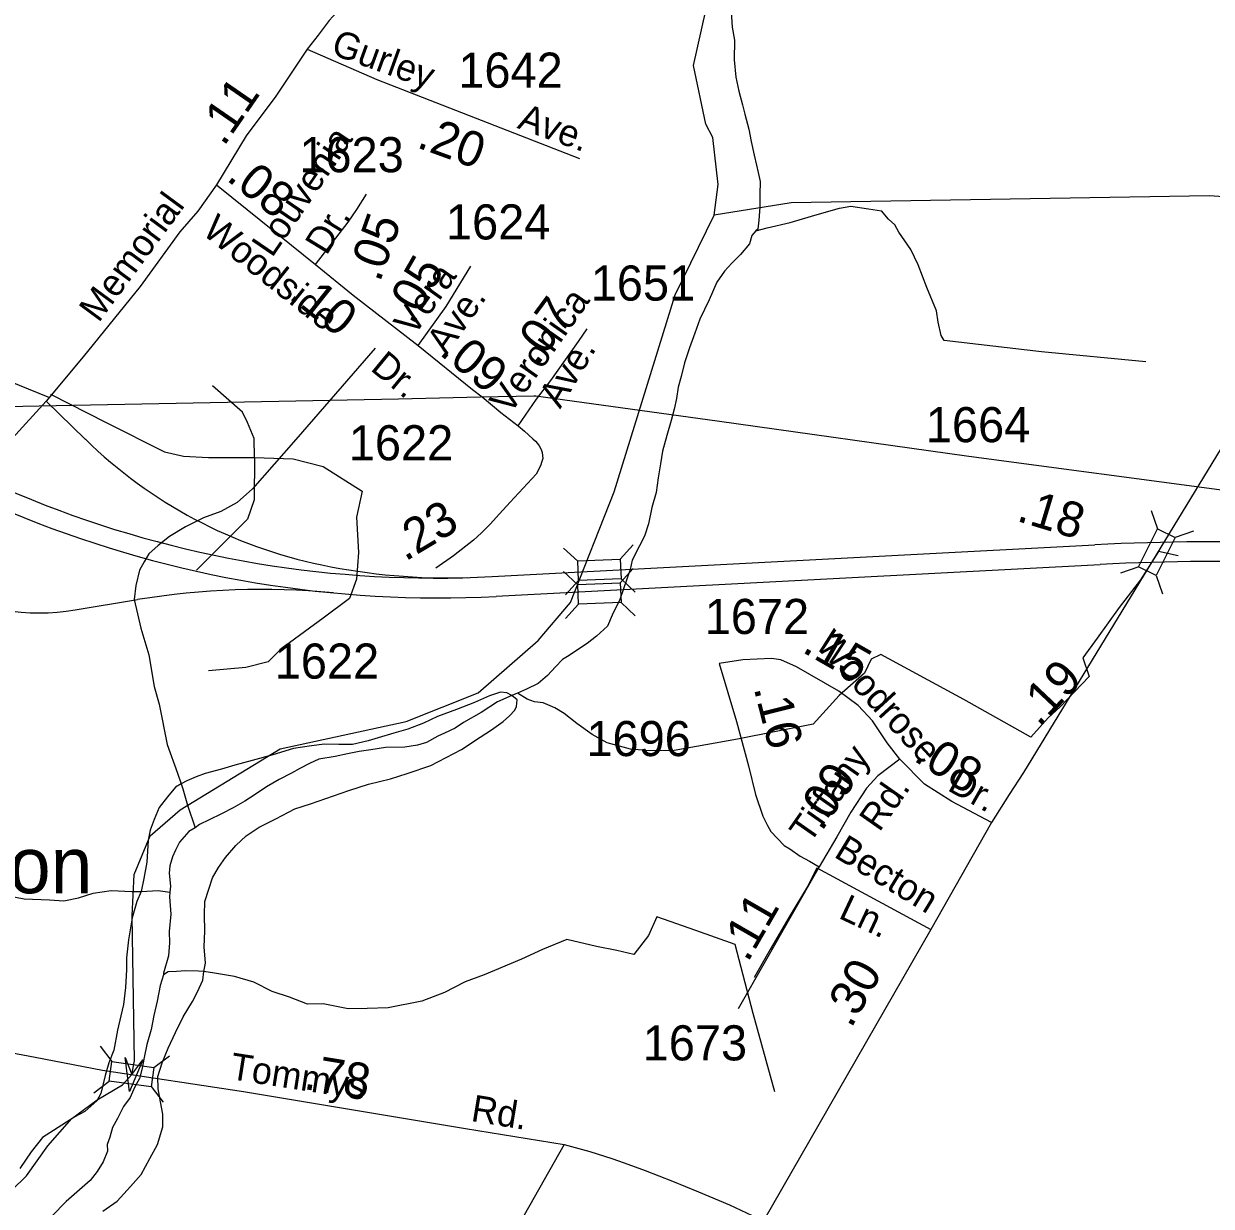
# Model space of a CAD drawing. Extents: x 2315291 to 2336543, y 597177 to 615230.
# Drawn here: x 2317521 to 2321750, y 606517 to 610727 of the extents above; entities that cross this region are included whole.
import ezdxf

# ---------------------------------------------------------------- set-up
doc = ezdxf.new("R2010")
doc.units = 0
for name, color, linetype in [('Exist Civil Demographics Community Label', 7, 'Continuous'), ('Exist Hydrographic Creek Single Shore', 7, 'Continuous'), ('Exist Hydrographic Misc Water Feature', 7, 'Continuous'), ('Exist Road Non-System Type 51', 7, 'Continuous'), ('Exist Road Non-System Type 51 Label', 7, 'Continuous'), ('Exist Road Primary US Attributed', 7, 'Continuous'), ('Exist Road Secondary Mileage Hundredths English Label', 7, 'Continuous'), ('Exist Road Secondary Structure Standard Bridge Attributed CELL', 7, 'Continuous'), ('Exist Road Secondary Structure Standard Bridge CELL', 7, 'Continuous'), ('Exist Road Secondary Type 51 Attributed', 7, 'Continuous'), ('Exist Road Secondary Type 51 Label', 7, 'Continuous'), ('Exist Road Secondary Type 51 Number Label', 7, 'Continuous'), ('Exist Utilities Electrical Transmission Line', 7, 'Continuous')]:
    doc.layers.add(name, color=color, linetype=linetype)

msp = doc.modelspace()

# ---------------------------------------------------------------- linework, layer by layer
at = {"layer": 'Exist Hydrographic Creek Single Shore'}
for points in [[(2319979.2, 610046.1), (2319994.3, 610155), (2319975.3, 610321.6), (2319950.2, 610369.8), (2319906.2, 610578.1), (2319995.9, 610982.4), (2320039.3, 611136.1), (2319944.8, 611360.6), (2319982.2, 611602.9), (2319883.7, 611839.2)], [(2317204.2, 606258.5), (2317425.2, 606522.7), (2317529.8, 606625.3), (2317606.2, 606732), (2317692.2, 606828.6), (2317781.7, 606896), (2317872.2, 606949.3), (2317905.4, 606985.5), (2317914.4, 607034.8), (2317906.3, 607550.3), (2317913.3, 607698.2), (2317970.3, 607835.1), (2318077.3, 607928.1), (2318433.3, 608145.9), (2318882.1, 608242.8), (2319139.3, 608345), (2319353.1, 608531), (2319468.2, 608666.9), (2319623.2, 609060.4), (2319840.3, 609761.6), (2319979.2, 610046.1)]]:
    msp.add_lwpolyline(points, dxfattribs=at)
at = {"layer": 'Exist Hydrographic Misc Water Feature'}
for points in [[(2320031.5, 610941.8), (2320034.7, 610910.4), (2320033.7, 610840.4), (2320040.5, 610770.5), (2320043.3, 610714.5), (2320051.5, 610668.6), (2320050.5, 610598.7), (2320057.1, 610536.8), (2320067.5, 610487), (2320080, 610438.9), (2320088.5, 610405.1), (2320102.8, 610351.5), (2320111.2, 610307.6), (2320121.9, 610259.4), (2320130.5, 610223.7), (2320136.8, 610197.9), (2320143, 610165.8), (2320141.6, 610119.8), (2320142, 610073.9), (2320138.7, 610027.7), (2320134.6, 609995.9), (2320128.4, 609990)], [(2322074.8, 610085.2), (2322043.2, 610093.6), (2321744.2, 610114.3), (2320253.3, 610090), (2319979.2, 610046.1)], [(2320128.4, 609990), (2320168.8, 610000.1), (2320250.2, 610019.1), (2320326.3, 610042.1), (2320388, 610060.4), (2320426, 610070.9), (2320465.7, 610077.5), (2320529.5, 610068.3), (2320575.5, 610060.6)], [(2321517.1, 609523), (2321145.3, 609559.1), (2320798.8, 609599.1), (2320788.5, 609617.3), (2320777.8, 609665.1), (2320771.3, 609705), (2320736.8, 609788.5), (2320705.9, 609868.2), (2320679.4, 609923.7), (2320637, 609985.2), (2320622.4, 610010.9), (2320600.3, 610030.9), (2320575.5, 610060.6)], [(2320128.4, 609990), (2320113.1, 609973.6), (2320105.5, 609943.5), (2320073.7, 609905.3), (2320042.3, 609874.8), (2320016.3, 609846.6), (2319989.2, 609806.5), (2319961.3, 609744.2), (2319928.3, 609675.8), (2319911.1, 609625.6), (2319891.4, 609573.5), (2319873.8, 609519.3), (2319862.5, 609471.2), (2319851, 609433.1), (2319845.7, 609393), (2319837.5, 609354.9), (2319826.2, 609314.8), (2319810.8, 609260.7), (2319795.6, 609204.7), (2319788.3, 609160.7), (2319780.3, 609110.4), (2319772.9, 609058.4), (2319757.5, 609004.3), (2319746.2, 608946.5), (2319730.8, 608902.1), (2319713.2, 608867.9), (2319687.8, 608817.7), (2319680, 608783.6), (2319668.5, 608749.7), (2319656.8, 608715.4), (2319643.3, 608677.3), (2319616, 608620.9), (2319600.2, 608582.7), (2319560.6, 608546.6), (2319527, 608520), (2319489.3, 608495.6), (2319463.5, 608477.7), (2319439.7, 608463.3), (2319414, 608436.8), (2319386.2, 608406.6), (2319352.5, 608378.4), (2319310.9, 608357.9), (2319279.1, 608343.5)], [(2318772, 609571.6), (2318489.7, 609246.7), (2318335.5, 609071.2), (2318280.3, 609022.3), (2318222.7, 608990), (2318161, 608967.3), (2318097.2, 608936.3), (2318039.6, 608902), (2317999.8, 608869.5), (2317966.4, 608839.2), (2317948.9, 608811), (2317932.7, 608781), (2317919.6, 608726.6), (2317914.3, 608676.8), (2317937.3, 608575.1), (2317966.4, 608479.5), (2317985.6, 608367.5), (2318002.3, 608303.8), (2318031.8, 608160.2), (2318068.5, 608058.6), (2318080.8, 608020.6)], [(2321632.5, 608832.4), (2321562.4, 608847.9), (2321497.6, 608747.3), (2321422.5, 608648.3), (2321343.8, 608539.7), (2321292.5, 608469.2), (2321315.5, 608403.3), (2321212.3, 608294.3), (2321168.9, 608255.8), (2321107.8, 608187.1), (2320868.7, 608320.5), (2320572.8, 608481.4)], [(2320572.8, 608481.4), (2320539.2, 608465), (2320515.4, 608414.6), (2320424.5, 608335.8), (2320331.6, 608233), (2320062.4, 608180.2), (2319837.3, 608139.5), (2319750.7, 608138.8), (2319681, 608143.9), (2319598.6, 608166.9), (2319544.5, 608196.5), (2319489.9, 608236), (2319445.6, 608271.5), (2319411.6, 608291.2), (2319371, 608308.6), (2319339.4, 608312.2), (2319313.4, 608321.8), (2319279.1, 608343.5)], [(2319259, 608335.2), (2319241.2, 608345.2), (2319218.8, 608346.9), (2319179.5, 608334.2), (2319125.5, 608309.9), (2319061.6, 608285.1), (2318993.7, 608260.4), (2318944.3, 608236.2), (2318888.5, 608215.4), (2318838.5, 608201), (2318782.9, 608184.2), (2318746.8, 608173.9), (2318691.2, 608161.2), (2318643, 608160.7), (2318591.2, 608162.4), (2318545.4, 608155.9), (2318481.5, 608146.9), (2318407.4, 608124.3), (2318333.8, 608103.4), (2318272.5, 608086.7), (2318224.5, 608072.4), (2318166.5, 608057.6), (2318134.7, 608045.4), (2318100.9, 608031), (2318080.8, 608020.6)], [(2319259, 608335.2), (2319207.8, 608312.5), (2319149.9, 608274.2), (2319086.4, 608239.5), (2319056.6, 608219.3), (2319018.7, 608200.7), (2318994.9, 608190.5), (2318954.9, 608168.1), (2318923.1, 608157.9), (2318877.4, 608151.4), (2318809.3, 608150.6), (2318757.3, 608141.9), (2318715.4, 608135.6), (2318673.6, 608127.3), (2318629.7, 608118.5), (2318571.9, 608108.1), (2318538.1, 608093.7), (2318504.4, 608075.3), (2318474.5, 608059.1), (2318430.8, 608036.5), (2318384.7, 608010.2), (2318341.4, 607979.8), (2318307.8, 607959.3), (2318266, 607934.8), (2318224.3, 607914.3), (2318180.6, 607892.1), (2318146.8, 607875.7), (2318130.8, 607863.5)], [(2318162, 607351.9), (2318167.9, 607382.2), (2318163.2, 607440.1), (2318164.9, 607495.8), (2318163.8, 607553.9), (2318165.5, 607602), (2318179.2, 607646.1), (2318192.7, 607686.3), (2318214.5, 607722.3), (2318239.5, 607758.7), (2318275.6, 607801.1), (2318313.1, 607835.2), (2318358.6, 607866.1), (2318418.5, 607896.4), (2318486, 607931.3), (2318541.7, 607949.6), (2318678.7, 607997.2), (2318748.8, 608019.9), (2318826.4, 608039), (2318886.4, 608057.6), (2318969.9, 608086.4), (2319079.2, 608143.3), (2319146.6, 608186.3), (2319186.4, 608212.7), (2319228.1, 608243), (2319250, 608263.2), (2319269.5, 608283.4), (2319275.4, 608295.5), (2319277.3, 608319.5), (2319259, 608335.2)], [(2319279.1, 608343.5), (2319272.8, 608341.7), (2319259, 608335.2)], [(2318080.8, 608020.6), (2318061.5, 608008.5), (2318032, 607974.5), (2318002.3, 607936), (2317984.6, 607894), (2317971.1, 607855.9), (2317963.3, 607819.7), (2317958.4, 607741.8), (2317948.7, 607683.6), (2317939.3, 607637.6)], [(2318080.8, 608020.6), (2318087.4, 608003.1), (2318104, 607945), (2318130.8, 607863.5)], [(2318130.8, 607863.5), (2318108.9, 607851.4), (2318075.3, 607813), (2318061.5, 607784.7), (2318049.8, 607760.5), (2318040.4, 607728.6), (2318038.5, 607702.6), (2318043.3, 607656.5), (2318041.2, 607634.4)], [(2316547.6, 607694.6), (2316633.1, 607733.3), (2316704.3, 607768.3), (2316748.6, 607780.8), (2316782.2, 607789.1), (2316788.1, 607786.9), (2316880.2, 607778), (2316966.5, 607760.9), (2317040.4, 607749.8), (2317080.7, 607724.2), (2317145.3, 607693.1), (2317195.2, 607675.4), (2317241.5, 607657.9), (2317305.7, 607632.8), (2317381.6, 607631.6), (2317441.4, 607626.2), (2317521.8, 607611.3), (2317611.8, 607607.8), (2317663.5, 607604.5), (2317715.8, 607615.3), (2317767.5, 607631.9), (2317831.4, 607640.5), (2317905.3, 607637.1), (2317939.3, 607637.6)], [(2317939.3, 607637.6), (2317923.5, 607601.5), (2317906.3, 607543.2), (2317893.2, 607464.9), (2317886, 607401.1), (2317886.2, 607358.9), (2317882.7, 607295.3), (2317875.7, 607235.1), (2317866.1, 607194.8), (2317854.8, 607143), (2317841.5, 607072.8), (2317824.1, 607026.8), (2317810.3, 606982.6), (2317794.9, 606918.4), (2317781.2, 606892.1), (2317737.9, 606853.6), (2317702.3, 606835.5), (2317626.4, 606786.4), (2317587, 606761.9), (2317547.4, 606709.9), (2317506.2, 606651.3)], [(2317939.3, 607637.6), (2317999.4, 607640.4), (2318041.2, 607634.4)], [(2318041.2, 607634.4), (2318039.4, 607618.5), (2318044.5, 607556.5), (2318038.8, 607494.5), (2318039.4, 607454.6), (2318035.5, 607408.6), (2318018.5, 607346.7), (2318018.2, 607340.6)], [(2320195.5, 606924.1), (2320118.8, 607203.4), (2320054, 607448.3), (2319913.7, 607498.6), (2319775.1, 607547.4), (2319745.8, 607480.9), (2319692.9, 607412.6), (2319632.8, 607427.7), (2319560.2, 607441.1), (2319454.4, 607465.9), (2319368.7, 607431), (2319293.3, 607396.1), (2319159.8, 607340.7), (2319092.5, 607316), (2319088.2, 607313.8), (2319018.5, 607277.3), (2318938.9, 607246.3), (2318819, 607223.3), (2318743.3, 607220.2), (2318675.6, 607219.8), (2318587.1, 607236.8), (2318531.3, 607236.3), (2318467.1, 607261.3), (2318404.8, 607280.8), (2318340.2, 607314.1), (2318270.7, 607335.1), (2318200.3, 607346.5), (2318162, 607351.9)], [(2318018.2, 607340.6), (2318006.8, 607302.2), (2317995.3, 607246.4), (2317984, 607196.1), (2317974.4, 607146.1), (2317959, 607092), (2317949.8, 607046), (2317942, 607007.8), (2317932.7, 606971.9), (2317916.5, 606941.5), (2317899.3, 606903.6), (2317875.5, 606871.4), (2317854, 606828.8), (2317836.4, 606797), (2317826.9, 606762.8), (2317817.1, 606736.7), (2317818.9, 606712.9), (2317803.8, 606674.6), (2317781.8, 606640.2), (2317756.6, 606607.9), (2317671.3, 606533.1), (2317621.7, 606482.6)], [(2317801.7, 606498.5), (2317853.2, 606534.9), (2317900.5, 606587.4), (2317938.3, 606630), (2317969.2, 606686.2), (2317996.9, 606736.8), (2318016, 606798.8), (2318015.6, 606844.7), (2318007.2, 606888.5), (2317998.8, 606934.4), (2317997.9, 606978.3), (2318013.5, 607026.7), (2318035.1, 607079), (2318060.5, 607135.2), (2318087.8, 607191.5), (2318121.4, 607245.6), (2318139, 607279.9), (2318158.3, 607322), (2318162, 607351.9)], [(2318162, 607351.9), (2318142.5, 607354), (2318098, 607355.4), (2318064, 607352.8), (2318034.4, 607350.8), (2318018.2, 607340.6)]]:
    msp.add_lwpolyline(points, dxfattribs=at)
at = {"layer": 'Exist Road Non-System Type 51'}
msp.add_line((2319445.3, 606736.2), (2319024.4, 605995.8), dxfattribs=at)
for points in [[(2318342.9, 609182.4), (2318340.6, 609250.8), (2318317.8, 609307.8), (2318299.6, 609344.3), (2318192.4, 609437.8)], [(2317616, 609407.8), (2317814, 609307.8), (2318021.4, 609203), (2318089.8, 609187), (2318178.7, 609182.4), (2318342.9, 609182.4)], [(2318342.9, 609182.4), (2318340.6, 609032), (2318317.8, 608963.6), (2318274.5, 608920.3), (2318135.4, 608781.2)], [(2318342.9, 609182.4), (2318479.7, 609177.9), (2318586.8, 609150.5), (2318725.5, 609063.2)], [(2318725.5, 609063.2), (2318705.3, 608970.4), (2318712.2, 608845), (2318705.3, 608749.3), (2318680.3, 608680.9), (2318586.8, 608610.2), (2318436.3, 608500.8), (2318390.8, 608455.2), (2318311, 608434.7), (2318178.7, 608423.3)], [(2320345.5, 607721.2), (2320315.5, 607661.2), (2320248.8, 607551.1), (2320178.8, 607431), (2320122.1, 607330.9)], [(2320345.5, 607721.2), (2320750.6, 607501.9)]]:
    msp.add_lwpolyline(points, dxfattribs=at)
at = {"layer": 'Exist Road Primary US Attributed'}
for p, q in [((2315744.5, 609760.3), (2317547.6, 609032.6)), ((2315744.5, 609686.1), (2317520.5, 608969.3)), ((2317411.1, 609477.5), (2317612.1, 609396.9)), ((2317600.7, 609383.2), (2317740, 609247.4)), ((2319189, 608758.5), (2321335.1, 608871.6)), ((2319202.9, 608688.4), (2321354, 608801.7)), ((2317704, 608639.8), (2317925.9, 608676.5))]:
    msp.add_line(p, q, dxfattribs=at)
for centre, radius, start, end in [((2318926.4, 610465), 1700, 225.7419, 258.3175), ((2318986.7, 612598.5), 3845.3, 248.0219, 273.0159), ((2318995.6, 612624.1), 3941.2, 248.0219, 273.0159), ((2321750.2, 600992.5), 7890, 71.2898, 93.01588), ((2319034.6, 610988.1), 2234.2, 258.3175, 271.7047), ((2321761.8, 601060.6), 7751.8, 71.2898, 93.01588), ((2317575.5, 609417), 787.7, 241.9803, 279.393), ((2318366.6, 606012.4), 2700.3, 84.5661, 99.393)]:
    msp.add_arc(centre, radius, start, end, dxfattribs=at)
at = {"layer": 'Exist Road Secondary Structure Standard Bridge Attributed CELL'}
msp.add_lwpolyline([(2317944.3, 607037.5), (2317897.1, 606925.1), (2317881.8, 607046.1), (2317905.4, 606985.5)], close=True, dxfattribs=at)
at = {"layer": 'Exist Road Secondary Structure Standard Bridge CELL'}
for p, q in [((2321535.7, 608994.4), (2321557.9, 608929)), ((2321686.5, 608919.9), (2321621.2, 608897.8)), ((2319493.9, 608813.4), (2319443.2, 608860.2)), ((2319691.6, 608871.5), (2319644.9, 608820.8)), ((2319493.9, 608729.4), (2319443.2, 608776.2)), ((2319691.6, 608787.5), (2319644.9, 608736.8)), ((2321492.1, 608793), (2321426.8, 608770.8)), ((2319496.7, 608744.5), (2319450, 608693.8)), ((2319698.5, 608703.5), (2319647.7, 608750.3)), ((2321554, 608762.4), (2321576.2, 608697.1)), ((2319496.7, 608660.5), (2319450, 608609.7)), ((2319698.5, 608619.5), (2319647.7, 608666.3)), ((2317792.8, 607086.5), (2317834.5, 607031.6)), ((2317984.2, 607010.9), (2318039.1, 607052.7)), ((2317770.1, 606919.9), (2317825, 606961.6)), ((2317974.9, 606942.5), (2318016.7, 606887.6))]:
    msp.add_line(p, q, dxfattribs=at)
for points in [[(2321621.2, 608897.8), (2321554.3, 608762.3), (2321491, 608793.5), (2321557.9, 608929)], [(2319647.7, 608750.3), (2319496.7, 608744.2), (2319493.9, 608814.7), (2319644.9, 608820.8)], [(2319647.7, 608666.3), (2319496.7, 608660.1), (2319493.9, 608730.7), (2319644.9, 608736.8)], [(2317834.5, 607031.6), (2317984.3, 607011.2), (2317974.8, 606941.3), (2317825, 606961.6)]]:
    msp.add_lwpolyline(points, close=True, dxfattribs=at)
at = {"layer": 'Exist Road Secondary Type 51 Attributed'}
msp.add_line((2322116.9, 609760.3), (2321080.7, 608061.5), dxfattribs=at)
for points in [[(2319168.5, 611211), (2319078.5, 611146), (2318975.1, 611060.9), (2318861.8, 610975.8), (2318765.2, 610899.6), (2318687, 610827), (2318621.3, 610753.3), (2318608.7, 610739.2), (2318568.7, 610686.7), (2318530.5, 610637)], [(2318530.5, 610637), (2318417.9, 610469), (2318312.9, 610327.6), (2318206.6, 610154.2)], [(2318530.5, 610637), (2318778.6, 610529.1), (2319500, 610247.4)], [(2318206.6, 610154.2), (2318140.5, 610059.5), (2318076.3, 609986.8), (2317935.1, 609792), (2317731.7, 609540.9), (2317600.7, 609383.2), (2317480.8, 609251.5), (2317194.6, 608913.5), (2316902.6, 608562.2), (2316557.1, 608149.7), (2316392.1, 607937.8), (2316293.5, 607811.2)], [(2318206.6, 610154.2), (2318474.4, 609939.3), (2318560, 609869.6)], [(2318560, 609869.6), (2318675.5, 610020.3), (2318706.6, 610066.3), (2318741.2, 610120.1)], [(2318560, 609869.6), (2318693.3, 609761.3), (2318925.1, 609581)], [(2318925.1, 609581), (2319024.5, 609720.2), (2319112.6, 609863.6)], [(2319281.2, 609295.8), (2319346.4, 609390.2), (2319397.3, 609457.4), (2319496.3, 609595.2), (2319526.7, 609641.2)], [(2318925.1, 609581), (2319118.9, 609425.3), (2319152.7, 609398.3), (2319220.2, 609342.8), (2319281.2, 609295.8)], [(2319281.2, 609295.8), (2319304.2, 609276.8), (2319333.3, 609249.4), (2319342.9, 609241.2), (2319350.1, 609233.1), (2319356, 609223.9), (2319363.9, 609211.1), (2319366.4, 609200.2), (2319368.6, 609190.1), (2319368.9, 609179.7), (2319366.2, 609168.4), (2319361.2, 609153), (2319345.4, 609122.9), (2319299.5, 609073), (2319253, 609023.1), (2319215.5, 608982.6), (2319181.6, 608945.1), (2319150.3, 608914.9), (2319122.4, 608888.5), (2319051.5, 608832.2), (2318987.8, 608788.4)], [(2320640.6, 608108.2), (2320595.6, 608166.6), (2320543.9, 608245), (2320492.2, 608300.1), (2320423.9, 608350.1), (2320272.2, 608436.9), (2320217.1, 608461.9), (2320183.8, 608466.9), (2320082.1, 608461.9), (2319997.1, 608448.6)], [(2319997.1, 608448.6), (2320059.4, 608242.7), (2320101.9, 608084.6), (2320126.7, 607982.9), (2320152.8, 607905.9), (2320169.3, 607872.9), (2320181.4, 607850.8), (2320204.5, 607826.3), (2320229.1, 607801.7), (2320249.3, 607788.7), (2320285.4, 607762.7), (2320318.7, 607745.3), (2320353, 607724.7)], [(2320640.6, 608108.2), (2320562.2, 608048.8), (2320522.3, 608004.8), (2320466, 607919.6), (2320416.6, 607831.6), (2320353, 607724.7)], [(2320967.3, 607883), (2320825.6, 607958.1), (2320728.9, 608019.8), (2320640.6, 608108.2)], [(2321080.7, 608061.5), (2321030.7, 607983.1), (2320967.3, 607883)], [(2320967.3, 607883), (2320750.6, 607501.9), (2320155.8, 606464.6)], [(2316293.5, 607811.2), (2316495.8, 607665.7), (2316732.9, 607495.2), (2317014.6, 607294.2), (2317123, 607222.5), (2317190.2, 607182.1), (2317240.2, 607154.3), (2317289.1, 607131), (2317344.7, 607106.5), (2317404.7, 607082.3), (2317454.7, 607067.3), (2317561.4, 607047.3), (2317800.8, 607001.1)], [(2320353, 607724.7), (2320064.9, 607219.9)], [(2317800.8, 607001.1), (2318303.3, 606924.7), (2319093.5, 606793.7), (2319445.3, 606736.2), (2319537, 606711.2), (2319615.3, 606686.1), (2319658.7, 606671.1), (2319733.7, 606644.4), (2319831.3, 606606.3), (2319923.7, 606567.7), (2320033.8, 606521.3), (2320155.8, 606464.6)]]:
    msp.add_lwpolyline(points, dxfattribs=at)
at = {"layer": 'Exist Utilities Electrical Transmission Line'}
for points in [[(2319147.2, 609397.1), (2318855.8, 609390.3), (2317575, 609365)], [(2319344.2, 609400.7), (2319337.4, 609401.6), (2319147.2, 609397.1)], [(2321813.3, 609062.4), (2320886.9, 609186.2), (2319990.2, 609312.6), (2319344.2, 609400.7)], [(2317575, 609365), (2316413.6, 609342), (2315744.5, 609319.6)]]:
    msp.add_lwpolyline(points, dxfattribs=at)

# ---------------------------------------------------------------- texts
at = {"layer": 'Exist Civil Demographics Community Label'}
msp.add_text('Langston', height=200, dxfattribs=at).set_placement((2316664.7, 607631.2))
at = {"layer": 'Exist Road Non-System Type 51 Label'}
for s, rotation, p in [('Becton', 328.526, (2320402.2, 607762.7)), ('Ln.', 334.8757, (2320418.6, 607544.4))]:
    msp.add_text(s, height=95, rotation=rotation, dxfattribs=at).set_placement(p)
at = {"layer": 'Exist Road Secondary Mileage Hundredths English Label'}
for s, rotation, p in [('.11', 55.4002, (2318233.2, 610287.4)), ('.20', 340.0551, (2318916.1, 610288.2)), ('.08', 321.4528, (2318238.4, 610173)), ('.05', 70.4507, (2318788.7, 609803.7)), ('.05', 60.0804, (2318906.1, 609651.4)), ('.10', 321.4527, (2318460.8, 609752.1)), ('.07', 53.5451, (2319349.3, 609505.3)), ('.09', 320.4679, (2318996.9, 609552.3)), ('.18', 343.1922, (2321052.9, 608957.8)), ('.23', 31.0724, (2318879, 608810.9)), ('.15', 330.2396, (2320288.5, 608492.4)), ('.19', 46.6243, (2321136.8, 608220)), ('.16', 284.2415, (2320119.9, 608361.5)), ('.08', 327.4486, (2320685.3, 608106.1)), ('.09', 55.8303, (2320362.1, 607847.8)), ('.11', 60.0736, (2320098.9, 607381.9)), ('.30', 60.6937, (2320467.2, 607147.2)), ('.78', 350.7064, (2318514.5, 606934.5))]:
    msp.add_text(s, height=125, rotation=rotation, dxfattribs=at).set_placement(p)
at = {"layer": 'Exist Road Secondary Type 51 Label'}
for s, rotation, p in [('Gurley', 340.0551, (2318610.4, 610620.5)), ('Ave.', 340.0551, (2319275, 610356.6)), ('Louvenia', 55.7123, (2318404.8, 609891.4)), ('Memorial', 53.6154, (2317787.3, 609659.9)), ('Woodside', 321.4527, (2318151.9, 609980.8)), ('Dr.', 58.5139, (2318598.7, 609899.3)), ('Vera', 54.495, (2318909.7, 609611.2)), ('Ave.', 55.1358, (2319026.4, 609545.1)), ('Veronica', 54.8771, (2319251.1, 609331.8)), ('Dr.', 320.4679, (2318751.7, 609495.7)), ('Ave.', 59.0366, (2319431, 609353.4)), ('Woodrose', 312.5095, (2320335.6, 608512.5)), ('Tiffany', 55.0221, (2320319.7, 607803.8)), ('Dr.', 330.4759, (2320806.5, 607999.8)), ('Rd.', 55.0221, (2320567.9, 607846.1)), ('Tommys', 351.0609, (2318251.5, 606970)), ('Rd.', 350.7064, (2319110.3, 606820.6))]:
    msp.add_text(s, height=95, rotation=rotation, dxfattribs=at).set_placement(p)
at = {"layer": 'Exist Road Secondary Type 51 Number Label'}
for s, p in [('1642', (2319068.3, 610499.5)), ('1623', (2318502.2, 610198.5)), ('1624', (2319024.3, 609959.1)), ('1651', (2319539.9, 609741.4)), ('1664', (2320733.4, 609237.2)), ('1622', (2318678.3, 609172.7)), ('1672', (2319945.8, 608554.2)), ('1622', (2318414.5, 608395.3)), ('1696', (2319524.4, 608119.4)), ('1673', (2319724.9, 607035.9))]:
    msp.add_text(s, height=125, dxfattribs=at).set_placement(p)

doc.saveas('drawing.dxf')
